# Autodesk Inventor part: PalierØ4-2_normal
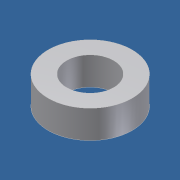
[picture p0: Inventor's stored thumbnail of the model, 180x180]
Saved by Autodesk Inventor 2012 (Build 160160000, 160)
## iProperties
Created: 2011-07
Part Number: PalierØ4-2_normal
Document SubType Name: Modeling
Designer: domi
Density: 1 g/cm^3
Material: Par défaut
Author: domi
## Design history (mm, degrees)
sketch "Esquisse1"
  geometry: C1 r 2.1 at (0, 0); C2 r 3.75 at (0, 0); 1 further point
  constraints: 2 centre point, 2 coincident
  dimensions: "d0" = 7.5 diameter of C2; "d1" = 4.2 diameter of C1
extrude "Pallier" new body sketch "Esquisse1" distance "d2" = 2.5; taper "d3" = 0 deg
node "Solide1"
node "Corps solides"
node "Corps surfaciques"
